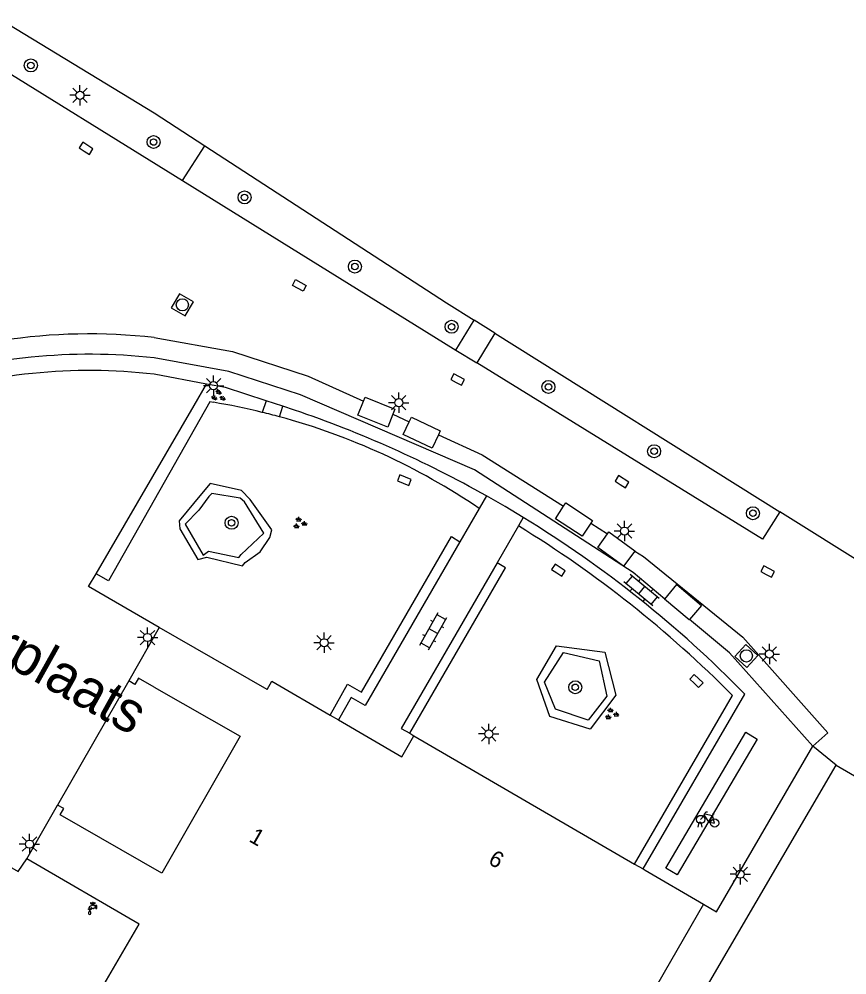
# Model space of a CAD drawing. Extents: x 136000 to 141014, y 402000 to 403500.
# Drawn here: x 137991.7 to 138042.5, y 402368.9 to 402427.6 of the extents above; entities that cross this region are included whole.
import ezdxf

# ---------------------------------------------------------------- set-up
doc = ezdxf.new("R2010")
doc.units = 0
for name, color, linetype in [('gg-afsc-hekwerk', 7, 'Continuous'), ('gg-afsc-muur', 7, 'Continuous'), ('gg-anno-huisnummerreeks BGT', 7, 'Continuous'), ('gg-anno-openbare ruimte label', 7, 'Continuous'), ('gg-bbg-hoofdgebouw', 7, 'Continuous'), ('gg-bbg-onder overbouw', 7, 'Continuous'), ('gg-bbg-pand overbouw', 7, 'Continuous'), ('gg-knt-verharding', 7, 'Continuous'), ('gg-knt-verharding nz', 7, 'Continuous'), ('gt-afsc-boombescherming', 7, 'Continuous'), ('gt-grn-groengrens', 7, 'Continuous'), ('gt-grn-weggrens', 7, 'Continuous'), ('gt-symb-boom', 7, 'Continuous'), ('gt-symb-fietsenrek', 7, 'Continuous'), ('gt-symb-groenvak', 7, 'Continuous'), ('gt-symb-klinker verharding', 7, 'Continuous'), ('gt-symb-kolk', 7, 'Continuous'), ('gt-symb-kolk center center', 7, 'Continuous'), ('gt-symb-lichtmast', 7, 'Continuous'), ('gt-symb-rioolschacht', 7, 'Continuous'), ('gt-symb-watertappunt', 7, 'Continuous')]:
    doc.layers.add(name, color=color, linetype=linetype)

# ---------------------------------------------------------------- blocks, each defined once
blk = doc.blocks.new('gt0-KOLK')
at = {"layer": 'gt-symb-kolk'}
blk.add_lwpolyline([(0, 0), (0.375, 0), (0.375, 0.4), (-0.375, 0.4), (-0.375, 0), (0, 0)], dxfattribs=at)
blk = doc.blocks.new('gt0-FREK')
at = {"layer": 'gt-symb-fietsenrek'}
for p, q in [((0.259, 0.762), (0.294, 0.823)), ((0.54, 0.335), (0.259, 0.762)), ((0.294, 0.823), (0.767, 0.714)), ((0.767, 0.714), (0.54, 0.335)), ((0.757, 0.841), (0.866, 0.816)), ((0.767, 0.714), (0.84, 0.822)), ((0.895, 0.252), (0.767, 0.714))]:
    blk.add_line(p, q, dxfattribs=at)
for points in [[(0.036, 0.476), (0.228, 0.708), (0.259, 0.762)], [(0.294, 0.823), (0.36, 0.937), (0.452, 0.935)], [(-0.124, 0), (-0.047, 0.312), (0.053, 0.312), (0.12, 0)], [(0.54, 0.335), (0.555, 0.305), (0.895, 0.252)]]:
    blk.add_lwpolyline(points, dxfattribs=at)
for centre in [(0.036, 0.476), (0.895, 0.252)]:
    blk.add_circle(centre, 0.252, dxfattribs=at)
blk = doc.blocks.new('gt0-LMAST')
at = {"layer": 'gt-symb-lichtmast'}
for p, q in [((-0.005, 0.246), (-0.005, 0.621)), ((-0.182, 0.173), (-0.447, 0.438)), ((0.172, 0.173), (0.437, 0.438)), ((-0.255, -0.004), (-0.63, -0.004)), ((-0.182, -0.181), (-0.447, -0.446)), ((-0.005, -0.254), (-0.005, -0.629)), ((0.437, -0.446), (0.172, -0.181)), ((0.245, -0.004), (0.62, -0.004))]:
    blk.add_line(p, q, dxfattribs=at)
blk.add_circle((-0.005, -0.004), 0.25, dxfattribs=at)
blk = doc.blocks.new('gt0-GRVAK')
at = {"layer": 'gt-symb-groenvak'}
for p, q in [((-0.11, 0.189), (-0.228, 0.24)), ((-0.182, 0.153), (0.088, 0.153)), ((-0.091, 0.211), (-0.156, 0.322)), ((-0.047, 0.214), (-0.047, 0.393)), ((-0.004, 0.211), (0.061, 0.322)), ((0.015, 0.189), (0.133, 0.24)), ((0.262, -0.052), (0.197, 0.059)), ((0.305, -0.049), (0.305, 0.13)), ((0.349, -0.052), (0.414, 0.059)), ((-0.245, -0.228), (-0.363, -0.177)), ((-0.318, -0.264), (-0.047, -0.264)), ((-0.226, -0.206), (-0.291, -0.095)), ((-0.183, -0.203), (-0.183, -0.024)), ((-0.139, -0.206), (-0.074, -0.095)), ((-0.12, -0.228), (-0.002, -0.177)), ((0.243, -0.074), (0.125, -0.023)), ((0.17, -0.11), (0.441, -0.11)), ((0.368, -0.074), (0.486, -0.023))]:
    blk.add_line(p, q, dxfattribs=at)
blk = doc.blocks.new('gt0-BOOM')
at = {"layer": 'gt-symb-boom'}
for radius in [0.4, 0.2]:
    blk.add_circle((0, 0), radius, dxfattribs=at)
blk = doc.blocks.new('gt0-WTP')
at = {"layer": 'gt-symb-watertappunt'}
for p, q in [((-0.141, 0.229), (-0.141, 0.214)), ((-0.141, 0.229), (-0.141, 0.214)), ((-0.125, 0.198), (-0.041, 0.207)), ((-0.125, 0.198), (-0.041, 0.207)), ((-0.042, 0.234), (-0.124, 0.243)), ((-0.042, 0.234), (-0.124, 0.243)), ((-0.024, 0.244), (-0.031, 0.238)), ((-0.024, 0.244), (-0.031, 0.238)), ((-0.019, 0.266), (-0.019, 0.256)), ((-0.019, 0.266), (-0.019, 0.256)), ((-0.017, 0.184), (-0.018, 0.164)), ((-0.017, 0.184), (-0.018, 0.164)), ((0.022, 0.164), (0.021, 0.183)), ((0.022, 0.164), (0.021, 0.183)), ((0.023, 0.256), (0.024, 0.267)), ((0.023, 0.256), (0.024, 0.267)), ((0.035, 0.238), (0.028, 0.245)), ((0.035, 0.238), (0.028, 0.245)), ((0.128, 0.243), (0.046, 0.233)), ((0.128, 0.243), (0.046, 0.233)), ((0.046, 0.206), (0.129, 0.198)), ((0.046, 0.206), (0.129, 0.198)), ((0.145, 0.213), (0.145, 0.228)), ((0.145, 0.213), (0.145, 0.228)), ((0.183, 0.079), (0.183, -0.086)), ((0.183, 0.079), (0.183, -0.086)), ((0.244, 0.089), (0.193, 0.089)), ((0.244, 0.089), (0.193, 0.089)), ((0.254, -0.086), (0.254, 0.079)), ((0.254, -0.086), (0.254, 0.079)), ((-0.251, -0.124), (-0.126, -0.124)), ((-0.251, -0.124), (-0.126, -0.124)), ((0.193, -0.096), (0.244, -0.096)), ((0.193, -0.096), (0.244, -0.096))]:
    blk.add_line(p, q, dxfattribs=at)
for points in [[(0.078, -0.063), (0.172, -0.063), (0.172, 0.059), (0.092, 0.059), (0.072, 0.074), (0.053, 0.089), (0.054, 0.111), (-0.048, 0.111), (-0.049, 0.089), (-0.09, 0.059)], [(0.078, -0.063), (0.172, -0.063), (0.172, 0.059), (0.092, 0.059), (0.072, 0.074), (0.053, 0.089), (0.054, 0.111), (-0.048, 0.111), (-0.049, 0.089), (-0.09, 0.059)], [(-0.028, 0.154), (-0.059, 0.154), (-0.059, 0.124), (0.064, 0.124), (0.064, 0.154), (0.032, 0.154)], [(-0.028, 0.154), (-0.059, 0.154), (-0.059, 0.124), (0.064, 0.124), (0.064, 0.154), (0.032, 0.154)], [(-0.03, 0.196), (-0.03, 0.194), (-0.027, 0.194)], [(-0.03, 0.196), (-0.03, 0.194), (-0.027, 0.194)], [(0.031, 0.193), (0.035, 0.193), (0.035, 0.196)], [(0.031, 0.193), (0.035, 0.193), (0.035, 0.196)], [(-0.121, -0.355), (-0.189, -0.203), (-0.267, -0.348)], [(-0.121, -0.355), (-0.189, -0.203), (-0.267, -0.348)]]:
    blk.add_lwpolyline(points, dxfattribs=at)
blk.add_lwpolyline([(-0.269, -0.13), (-0.109, -0.13), (-0.109, -0.16), (-0.269, -0.16)], close=True, dxfattribs=at)
blk.add_lwpolyline([(-0.269, -0.13), (-0.109, -0.13), (-0.109, -0.16), (-0.269, -0.16)], close=True, dxfattribs=at)
for centre, radius, start, end in [((-0.065, -0.125), 0.186, 97.63906, 179.52381), ((-0.065, -0.125), 0.186, 97.63906, 179.52381), ((-0.126, 0.228), 0.015, 83.50257, 178.15351), ((-0.126, 0.228), 0.015, 83.50257, 178.15351), ((-0.126, 0.213), 0.015, 178.15351, 275.57946), ((-0.126, 0.213), 0.015, 178.15351, 275.57946), ((-0.04, 0.249), 0.015, 263.50257, 310.25348), ((-0.04, 0.249), 0.015, 263.50257, 310.25348), ((-0.04, 0.197), 0.01, 358.80723, 95.57946), ((-0.04, 0.197), 0.01, 358.80723, 95.57946), ((-0.028, 0.164), 0.01, 270, 358.80723), ((-0.028, 0.164), 0.01, 270, 358.80723), ((-0.027, 0.184), 0.01, 358.80723, 88.80723), ((-0.027, 0.184), 0.01, 358.80723, 88.80723), ((-0.034, 0.255), 0.015, 313.74431, 2.48805), ((-0.034, 0.255), 0.015, 313.74431, 2.48805), ((0.002, 0.256), 0.0242, 27.67782, 154.22328), ((0.002, 0.256), 0.0242, 27.67782, 154.22328), ((0.031, 0.183), 0.01, 91.19277, 181.19277), ((0.031, 0.183), 0.01, 91.19277, 181.19277), ((0.032, 0.164), 0.01, 181.19277, 270), ((0.032, 0.164), 0.01, 181.19277, 270), ((0.038, 0.256), 0.015, 177.51195, 226.25569), ((0.038, 0.256), 0.015, 177.51195, 226.25569), ((0.046, 0.249), 0.0156, 223.37933, 270.13024), ((0.046, 0.249), 0.0156, 223.37933, 270.13024), ((0.045, 0.196), 0.01, 84.42054, 181.19277), ((0.045, 0.196), 0.01, 84.42054, 181.19277), ((0.13, 0.228), 0.015, 1.84649, 96.49743), ((0.13, 0.228), 0.015, 1.84649, 96.49743), ((0.13, 0.213), 0.015, 264.42054, 1.84649), ((0.13, 0.213), 0.015, 264.42054, 1.84649), ((0.193, 0.079), 0.01, 90, 180), ((0.193, 0.079), 0.01, 90, 180), ((0.244, 0.079), 0.01, 0, 90), ((0.244, 0.079), 0.01, 0, 90), ((-0.196, -0.388), 0.0814, 151.16535, 24.05764), ((-0.196, -0.388), 0.0814, 151.16535, 24.05764), ((-0.074, -0.114), 0.0533, 95.91372, 190.22525), ((-0.074, -0.114), 0.0533, 95.91372, 190.22525), ((0, 0), 0.1, 217.59763, 321.3207), ((0, 0), 0.1, 217.59763, 321.3207), ((0.193, -0.086), 0.01, 180, 270), ((0.193, -0.086), 0.01, 180, 270), ((0.244, -0.086), 0.01, 270, 0), ((0.244, -0.086), 0.01, 270, 0)]:
    blk.add_arc(centre, radius, start, end, dxfattribs=at)
blk = doc.blocks.new('gt0-RS')
at = {"layer": 'gt-symb-rioolschacht'}
blk.add_lwpolyline([(-0.5, -0.5), (0.5, -0.5), (0.5, 0.5), (-0.5, 0.5)], close=True, dxfattribs=at)
blk.add_circle((0, 0), 0.375, dxfattribs=at)
blk = doc.blocks.new('gt0-KOLKCC')
at = {"layer": 'gt-symb-kolk center center'}
blk.add_lwpolyline([(-0.375, 0.2), (0.375, 0.2), (0.375, -0.2), (-0.375, -0.2)], close=True, dxfattribs=at)
blk = doc.blocks.new('gt0-KL1')
at = {"layer": 'gt-symb-klinker verharding'}
for p, q in [((-1.15, 0.3), (1.15, 0.3)), ((-1, -0.3), (-1, 0.3)), ((-0.5, 0.3), (-0.5, 0.45)), ((0, -0.3), (0, 0.3)), ((0.5, 0.3), (0.5, 0.45)), ((1, -0.3), (1, 0.3)), ((-1.15, -0.3), (1.15, -0.3)), ((-0.5, -0.45), (-0.5, -0.3)), ((0.5, -0.45), (0.5, -0.3))]:
    blk.add_line(p, q, dxfattribs=at)

msp = doc.modelspace()

# ---------------------------------------------------------------- linework, layer by layer
at = {"layer": 'gg-afsc-hekwerk'}
msp.add_line((138041.892, 402381.79), (138045.53, 402379.667), dxfattribs=at)
msp.add_lwpolyline([(138030.63, 402357.914), (138028.649, 402359.103), (138041.892, 402381.79)], dxfattribs=at)
at = {"layer": 'gg-afsc-muur'}
for p, q in [((138012.501, 402403.307), (138012.852, 402404.169)), ((138015.287, 402402.121), (138015.663, 402402.898)), ((138024.64, 402396.927), (138025.149, 402397.708)), ((138027.24, 402395.172), (138027.839, 402396.009))]:
    msp.add_line(p, q, dxfattribs=at)
for points in [[(138012.852, 402404.169), (138012.949, 402404.409), (138014.774, 402403.668), (138014.652, 402403.355)], [(138014.652, 402403.355), (138014.346, 402402.574), (138012.501, 402403.307)], [(138015.663, 402402.898), (138015.801, 402403.182), (138017.57, 402402.336), (138017.455, 402402.087)], [(138017.455, 402402.087), (138017.074, 402401.267), (138015.287, 402402.121)], [(138025.149, 402397.708), (138025.289, 402397.923), (138026.93, 402396.831), (138026.816, 402396.655)], [(138026.816, 402396.655), (138026.296, 402395.856), (138024.64, 402396.927)], [(138027.839, 402396.009), (138027.923, 402396.127), (138029.532, 402394.966), (138029.519, 402394.948)], [(138029.519, 402394.948), (138028.831, 402394.012), (138027.24, 402395.172)], [(138031.366, 402392.004), (138032.099, 402392.902), (138033.61, 402391.613), (138032.884, 402390.741)], [(138032.884, 402390.741), (138032.862, 402390.714), (138031.352, 402391.987), (138031.366, 402392.004)]]:
    msp.add_lwpolyline(points, dxfattribs=at)
at = {"layer": 'gg-bbg-hoofdgebouw'}
for p, q in [((138000.305, 402390.247), (137998.431, 402386.975)), ((138006.941, 402386.45), (138000.305, 402390.247)), ((138010.799, 402384.871), (138011.317, 402384.569)), ((138015.951, 402383.6), (138029.505, 402375.714)), ((137992.17, 402376.041), (137994.058, 402379.338)), ((138029.505, 402375.714), (138030.024, 402375.412)), ((138030.024, 402375.412), (138030.15, 402375.339)), ((138030.15, 402375.339), (138033.741, 402373.25)), ((138033.741, 402373.25), (138022.397, 402353.534))]:
    msp.add_line(p, q, dxfattribs=at)
for points in [[(138006.941, 402386.45), (138007.231, 402386.95), (138010.799, 402384.871)], [(138011.317, 402384.569), (138015.211, 402382.3), (138015.951, 402383.6)], [(138022.397, 402353.534), (137996.927, 402368.34), (137999.071, 402372.029), (137992.17, 402376.041)]]:
    msp.add_lwpolyline(points, dxfattribs=at)
at = {"layer": 'gg-bbg-onder overbouw'}
for points in [[(138000, 402386.585), (137999.028, 402387.141), (137998.809, 402386.759), (137998.431, 402386.975)], [(138000, 402386.585), (138005.274, 402383.567), (138000.467, 402375.165)], [(138000.467, 402375.165), (137994.221, 402378.739), (137994.439, 402379.121), (137994.058, 402379.338)]]:
    msp.add_lwpolyline(points, dxfattribs=at)
at = {"layer": 'gg-bbg-pand overbouw'}
msp.add_line((137998.431, 402386.975), (137994.058, 402379.338), dxfattribs=at)
at = {"layer": 'gg-knt-verharding'}
for p, q in [((138001.732, 402417.733), (138018.517, 402407.296)), ((138018.517, 402407.296), (138019.643, 402409.138)), ((138020.92, 402408.338), (138019.643, 402409.138)), ((138020.92, 402408.338), (138019.813, 402406.508)), ((138020.92, 402408.338), (138038.429, 402397.359)), ((138003.213, 402405.217), (138000, 402405.814)), ((138002.45, 402403.906), (138003.213, 402405.217)), ((137996.429, 402393.557), (138002.45, 402403.906)), ((138007.898, 402403.852), (138006.881, 402404.184)), ((138008.62, 402403.616), (138007.898, 402403.852)), ((138014.652, 402403.355), (138015.663, 402402.898)), ((138020.408, 402398.34), (138019.965, 402397.574)), ((138019.965, 402397.574), (138018.781, 402395.526)), ((138056.26, 402386.178), (138038.429, 402397.359)), ((138022.671, 402397.012), (138022.37, 402396.492)), ((138022.37, 402396.492), (138021.066, 402394.237)), ((138026.816, 402396.655), (138027.839, 402396.009)), ((138030.024, 402375.412), (138036.279, 402386.163)), ((138015.693, 402383.751), (138015.951, 402383.6))]:
    msp.add_line(p, q, dxfattribs=at)
for points in [[(137990.542, 402427.641), (137989.159, 402425.514), (138001.732, 402417.733)], [(137990.542, 402427.641), (138000, 402421.886), (138003.115, 402419.859)], [(138003.115, 402419.859), (138017.954, 402410.207), (138019.643, 402409.138)], [(138000, 402408.078), (138004.81, 402407.213), (138009.459, 402405.704), (138012.852, 402404.169)], [(138031.366, 402392.004), (138029.416, 402393.625), (138019.665, 402399.946), (138008.993, 402404.544), (138004.573, 402405.984), (138000, 402406.821)], [(138038.429, 402397.359), (138037.374, 402395.676), (138019.813, 402406.508)], [(138006.881, 402404.184), (138004.383, 402405), (138003.213, 402405.217)], [(138017.455, 402402.087), (138020.139, 402400.873), (138025.149, 402397.708)], [(138022.671, 402397.012), (138021.547, 402397.686), (138020.408, 402398.34)], [(138018.781, 402395.526), (138012.958, 402385.453), (138012.092, 402385.954), (138011.317, 402384.569)], [(138029.519, 402394.948), (138030.049, 402394.613), (138036.153, 402389.656), (138041.384, 402383.786), (138040.465, 402382.964)], [(138021.066, 402394.237), (138015.176, 402384.055), (138015.693, 402383.751)], [(138000.305, 402390.247), (137995.972, 402392.771), (137996.429, 402393.557)], [(138040.465, 402382.964), (138035.335, 402388.703), (138032.884, 402390.741)], [(137988.266, 402377.188), (137991.649, 402375.258), (137992.17, 402376.041)]]:
    msp.add_lwpolyline(points, dxfattribs=at)
for centre, radius, start, end in [((137996.049, 402372.321), 35.974, 83.69448, 98.66525), ((137993.89, 402389.156), 17.76, 94.70456, 148.4782), ((137996.052, 402372.197), 34.849, 83.49448, 95.96035), ((137993.891, 402389.153), 16.763, 94.67064, 148.28369), ((137996.052, 402372.29), 33.756, 83.2835, 95.99591), ((137985.827, 402336.884), 70.517, 60.63391, 71.14201), ((137985.782, 402336.783), 70.628, 44.35926, 58.51342)]:
    msp.add_arc(centre, radius, start, end, dxfattribs=at)
at = {"layer": 'gg-knt-verharding nz'}
msp.add_line((138018.517, 402407.296), (138019.813, 402406.508), dxfattribs=at)
msp.add_lwpolyline([(138036.338, 402383.813), (138037.033, 402383.396), (138032.113, 402375.044), (138031.417, 402375.461), (138036.338, 402383.813)], dxfattribs=at)
at = {"layer": 'gt-afsc-boombescherming'}
for points in [[(138005.357, 402398.674), (138003.435, 402399.094), (138002.898, 402398.471), (138001.527, 402396.815), (138001.567, 402396.312), (138002.675, 402394.422), (138003.229, 402394.576), (138005.422, 402394.051), (138005.583, 402394.245), (138006.516, 402394.905), (138007.091, 402395.789), (138007.223, 402396.25), (138005.895, 402398.119), (138005.357, 402398.674)], [(138005.276, 402398.198), (138003.545, 402398.498), (138003.347, 402398.295), (138002.74, 402397.463), (138001.909, 402396.601), (138003.001, 402394.698), (138003.333, 402394.952), (138005.202, 402394.56), (138005.331, 402394.74), (138006.727, 402396.053), (138005.536, 402397.982), (138005.276, 402398.198)], [(138024.718, 402389.127), (138027.677, 402388.732), (138028.354, 402386.102), (138026.788, 402384.007), (138024.295, 402384.785), (138023.507, 402387.048), (138024.718, 402389.127)], [(138023.969, 402386.884), (138025.142, 402388.719), (138027.339, 402388.205), (138027.81, 402386.04), (138026.646, 402384.548), (138024.656, 402385.24), (138023.969, 402386.884)]]:
    msp.add_lwpolyline(points, dxfattribs=at)
at = {"layer": 'gt-grn-groengrens'}
for p, q in [((138001.732, 402417.733), (138003.115, 402419.859)), ((138006.881, 402404.184), (138006.639, 402403.475)), ((138007.686, 402403.205), (138007.898, 402403.852)), ((138029.505, 402375.714), (138035.53, 402386.069))]:
    msp.add_line(p, q, dxfattribs=at)
for points in [[(138003.633, 402404.09), (138003.412, 402404.126), (137997.185, 402393.117), (137996.429, 402393.557)], [(138010.799, 402384.871), (138011.866, 402386.778), (138012.739, 402386.273), (138018.269, 402395.839), (138018.781, 402395.526)], [(138015.693, 402383.751), (138021.576, 402393.921), (138021.066, 402394.237)]]:
    msp.add_lwpolyline(points, dxfattribs=at)
for centre, radius, start, end in [((137996.927, 402363.659), 40.984, 76.29214, 80.58261), ((137997.428, 402365.591), 38.988, 74.74512, 76.33415), ((137996.893, 402363.467), 41.177, 55.9235, 74.80527), ((137985.809, 402336.811), 69.99, 44.73202, 58.50803)]:
    msp.add_arc(centre, radius, start, end, dxfattribs=at)
at = {"layer": 'gt-grn-weggrens'}
msp.add_line((138041.892, 402381.79), (138040.465, 402382.964), dxfattribs=at)
msp.add_lwpolyline([(138033.741, 402373.25), (138034.543, 402372.784), (138040.465, 402382.964)], dxfattribs=at)

# ---------------------------------------------------------------- block references
at = {"layer": 'gt-symb-boom'}
for p in [(137992.419, 402424.793), (137999.962, 402420.089), (138005.548, 402416.686), (138012.328, 402412.434), (138018.269, 402408.735), (138024.216, 402405.033), (138030.705, 402401.087), (138036.779, 402397.277), (138004.753, 402396.687), (138025.865, 402386.577)]:
    msp.add_blockref('gt0-BOOM', p, dxfattribs=at)
at = {"layer": 'gt-symb-fietsenrek'}
msp.add_blockref('gt0-FREK', (138033.527, 402377.981), dxfattribs=at)
at = {"layer": 'gt-symb-groenvak', "rotation": -20.482296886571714}
msp.add_blockref('gt0-GRVAK', (138003.921, 402404.477), dxfattribs=at)
at = {"layer": 'gt-symb-groenvak'}
for p in [(138008.925, 402396.662), (138028.081, 402384.93)]:
    msp.add_blockref('gt0-GRVAK', p, dxfattribs=at)
at = {"layer": 'gt-symb-klinker verharding'}
for p, rotation in [((138029.932, 402392.545), 140.27513746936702), ((138017.142, 402390.023), 60.53928638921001)]:
    msp.add_blockref('gt0-KL1', p, dxfattribs=dict(at, rotation=rotation))
at = {"layer": 'gt-symb-kolk'}
for p, rotation in [((137995.703, 402419.53), -32.75243944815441), ((138018.542, 402405.315), -28.61503162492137), ((138015.285, 402399.128), -22.461175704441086), ((138028.629, 402399.047), -32.625035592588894), ((138024.721, 402393.608), -32.46679945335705), ((138037.583, 402393.516), -28.564718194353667), ((138033.168, 402386.822), -43.25692965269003)]:
    msp.add_blockref('gt0-KOLK', p, dxfattribs=dict(at, rotation=rotation))
at = {"layer": 'gt-symb-kolk center center', "rotation": -28.82083594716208}
msp.add_blockref('gt0-KOLKCC', (138008.908, 402411.274), dxfattribs=at)
at = {"layer": 'gt-symb-lichtmast'}
for p in [(137995.44, 402422.965), (138003.65, 402405.117), (138015.025, 402404.073), (138028.891, 402396.181), (137999.592, 402389.64), (138010.441, 402389.318), (138037.794, 402388.627), (138020.556, 402383.714), (137992.342, 402376.944), (138036, 402375.095)]:
    msp.add_blockref('gt0-LMAST', p, dxfattribs=at)
at = {"layer": 'gt-symb-rioolschacht'}
for p, rotation in [((138001.728, 402410.082), -30.128600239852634), ((138036.373, 402388.505), -42.36616983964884)]:
    msp.add_blockref('gt0-RS', p, dxfattribs=dict(at, rotation=rotation))
at = {"layer": 'gt-symb-watertappunt'}
msp.add_blockref('gt0-WTP', (137996.23, 402373.084), dxfattribs=at)

# ---------------------------------------------------------------- texts
at = {"layer": 'gg-anno-huisnummerreeks BGT'}
for s, rotation, p in [('1', 330.2, (138005.757, 402377.139)), ('6', 329.8, (138020.455, 402375.773))]:
    msp.add_text(s, height=1, rotation=rotation, dxfattribs=at).set_placement(p)
at = {"layer": 'gg-anno-openbare ruimte label'}
msp.add_text('Theaterplaats', height=2.5, rotation=330.8, dxfattribs=at).set_placement((137980.781, 402393.564))

doc.saveas('drawing.dxf')
